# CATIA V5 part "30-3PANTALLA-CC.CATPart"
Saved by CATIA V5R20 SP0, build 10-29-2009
Part number: 30-3PANTALLA-CC
Revision: ANY
Definition: UNKNOWN
Nomenclature: 30-3PANTALLA-CC
Source: Unknown
Bounding box of the stored display mesh (mm): x 0 to 38.9, y -1 to 0.75, z -10.4 to 0
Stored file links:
  C:\Users\Utente\Desktop\IO LAVORO\3D X SITO CF\CUMSA\3D files CC\CCHS5328\30-3PANTALLA-CC.CATPart
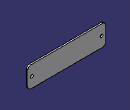
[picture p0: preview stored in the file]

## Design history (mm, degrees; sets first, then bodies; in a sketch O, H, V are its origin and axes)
Body1 "Cortar-Extruir1" (main body)
  Solid1: solid without history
